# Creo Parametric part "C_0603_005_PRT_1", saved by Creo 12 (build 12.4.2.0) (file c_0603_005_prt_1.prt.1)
Units: Custom; MM, KILOGRAM, SECS

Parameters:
  PTC_WM_ITERATION = "0"
  PTC_WM_VERSION = "-.0"
  PTC_WM_LIFECYCLE_STATE = "In Work"
  PTC_WM_LIFECYCLE = "MO_CADDocument"
  PTC_WM_CREATED_BY = "Maximilian Roepper (Z0017RMS: MO)"
  PTC_WM_CREATED_ON = "18-Sep-26 11:36:42 AM"
  PTC_WM_MODIFIED_BY = "Maximilian Roepper (Z0017RMS: MO)"
  PTC_WM_MODIFIED_ON = "18-Sep-26 11:36:46 AM"
  PDMLINKNUMBER = "PDM000071454825"
  PTC_WM_NAME = "c_0603_005_prt_1.prt"
  PTC_WM_NUMBER = "PDM000071454825"

Other parameters: WEIGHT, WEIGHT_FACTOR, WEIGHT_ADD, _MASS_TEMP, _DIFF_TEMP, MC_ERRORS, SUPPLIER

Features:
  1. coordinate system
  2. datum plane "PRT_YZ"
  3. datum plane "PRT_XY"
  4. datum plane "PRT_XZ"
  5. coordinate system
  6. datum axis
  7. datum axis
  8. datum axis
  9. coordinate system
  10. imported feature
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
Other named items: PRT, SIEMENS_MO, DRW_VIEW_ORG, PRT_X, PRT_Y, PRT_Z, CS0, ROUGH_GROB

Layers: 00_STD_CSYS-KSYS, 01_STD_PLANES-EBENEN, 02_STD_AXES-ACHSEN, 03_STD_CSYS-KSYS, 24_IMPORT_FEAT-IMPORT_KE

Surfaces: 16 plane, 12 cylinder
